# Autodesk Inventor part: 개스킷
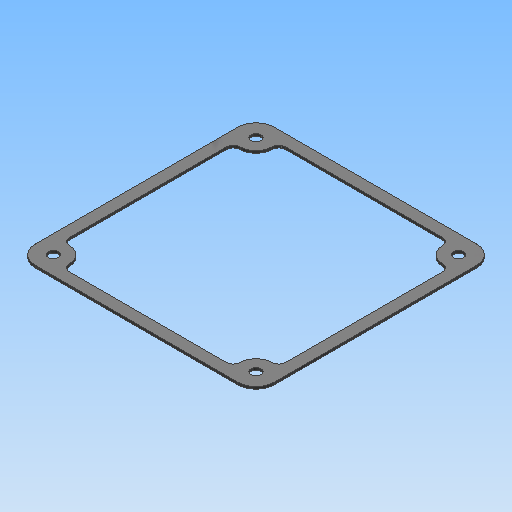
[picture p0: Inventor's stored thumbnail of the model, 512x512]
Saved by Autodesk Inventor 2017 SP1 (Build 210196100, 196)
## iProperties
Created: 2019-04
Part Number: 개스킷
Material: 고무
Document SubType Name: Modeling
Designer: mduedu
Density: 0.93 g/cm^3
Mass: 2.09699 g
Surface Area: 53.3016 cm^2
Volume: 2.25483 cm^3
Appearance: 고무 - 검은색 - 버전 1.1
Author: mduedu
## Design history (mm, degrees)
sketch "스케치1"
  geometry: L1 (52.5, 52.5)-(-52.5, 52.5); L2 (-52.5, 52.5)-(-52.5, -52.5); L3 (-52.5, -52.5)-(52.5, -52.5); L4 (52.5, -52.5)-(52.5, 52.5); L5 (52.5, 52.5)-(-52.5, -52.5); L6 (-52.5, 52.5)-(52.5, -52.5); 1 further point
  constraints: 12 end point, 2 midpoint, 2 parallel, 1 horizontal, 1 perpendicular
  dimensions: "d0" = 105 distance of L3.end L2.end; "d1" = 105 distance of L2.end L1.end
extrude "돌출1" new body sketch "스케치1" distance "d2" = 1; taper "d3" = 0 deg
sketch "스케치2"
  geometry: L1 (-52.5, -52.5)-(52.5, -52.5) reference; L2 (52.5, -52.5)-(52.5, 52.5) reference; L3 (52.5, 52.5)-(-52.5, 52.5) reference; L4 (-52.5, 52.5)-(-52.5, -52.5) reference; L5 (-47.5, 47.5)-(47.5, 47.5); L6 (47.5, 47.5)-(47.5, -47.5); L7 (47.5, -47.5)-(-47.5, -47.5); L8 (-47.5, -47.5)-(-47.5, 47.5); 1 further point
  constraints: 8 end point, 3 other
  dimensions: "d4" = 5 distance between parallel lines of L5 L3
extrude "돌출2" cut sketch "스케치2" stored distance "d5" = 1; taper "d6" = 0 deg
fillet "모깎기1" dims "d7" = 8
sketch "스케치3"
  geometry: C1 r 7 at (-44.5, 44.5); C2 r 7 at (-44.5, -44.5); C3 r 7 at (44.5, -44.5); C4 r 7 at (44.5, 44.5); A1 r 8 centre (-44.5, 44.5) between (-44.5, 52.5) and (-52.5, 44.5) reference; A2 r 8 centre (-44.5, -44.5) between (-52.5, -44.5) and (-44.5, -52.5) reference; A3 r 8 centre (44.5, -44.5) between (44.5, -52.5) and (52.5, -44.5) reference; A4 r 8 centre (44.5, 44.5) between (52.5, 44.5) and (44.5, 52.5) reference; 1 further point
  constraints: 4 centre point, 4 coincident, 3 equal radius
  dimensions: "d18" = 14 diameter of C1
extrude "돌출3" join sketch "스케치3" stored distance "d8" = 1; taper "d9" = 0 deg
fillet "모깎기2" dims "d10" = 3
sketch "스케치4"
  geometry: A1 r 8 centre (-44.5, 44.5) between (-44.5, 52.5) and (-52.5, 44.5) reference; A2 r 8 centre (44.5, 44.5) between (52.5, 44.5) and (44.5, 52.5) reference; A3 r 8 centre (44.5, -44.5) between (44.5, -52.5) and (52.5, -44.5) reference; A4 r 8 centre (-44.5, -44.5) between (-52.5, -44.5) and (-44.5, -52.5) reference; 5 further points
  constraints: 4 coincident
hole "구멍1" sketch "스케치4" at (-44.5, 44.5), (44.5, 44.5), (44.5, -44.5), (-44.5, -44.5) diameter "d11" = 4.5; stored, may be unused: countersink angle "d15" = 90 deg, drill point angle "d17" = 118 deg; dims "d12" = 6, "d13" = 4, "d14" = 2, "d16" = 8
node "솔리드1"
node "투영된 루프1"
